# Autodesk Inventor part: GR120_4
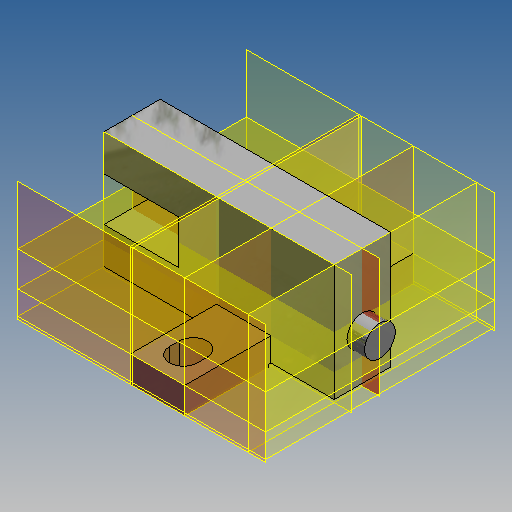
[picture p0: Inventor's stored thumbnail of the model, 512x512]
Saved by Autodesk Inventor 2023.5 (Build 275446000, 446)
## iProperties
Part Number: GR120_4
Material: Allgemein
Document SubType Name: Modellieren
Designer: WH
Appearance: Vorgabe
Author: WH
NB: GR120_4
NN: GR120
NBSYN: $CNSORDERNO._4
LINA: GR120_4
CATALOG: GIGAGER
CNSORDERNO: GR120
SCS: GR120
SUPPLIER: SAINI
ARTICLENO: GR120_4
BOMINFO: GR120_4
CREATOR: CADENAS GmbH
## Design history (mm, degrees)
feature "GR120_4"
node "A_1"
node "A_2"
node "4_ZAXS"
node "RIGHT"
node "TOP"
node "FRONT"
node "DTM1"
node "DTM2"
node "DTM3"
node "DTM4"
node "DTM5"
node "DTM6"
node "DTM7"
node "DTM8"
node "DTM9"
node "DTM10"
node "DTM11"
node "DTM12"
node "DTM13"
node "DTM14"
node "4_XPLN"
node "4_YPLN"
node "4_ZPLN"
node "Volumenkörper1"
node "Volumenkörper"
node "Flächenkörper"
